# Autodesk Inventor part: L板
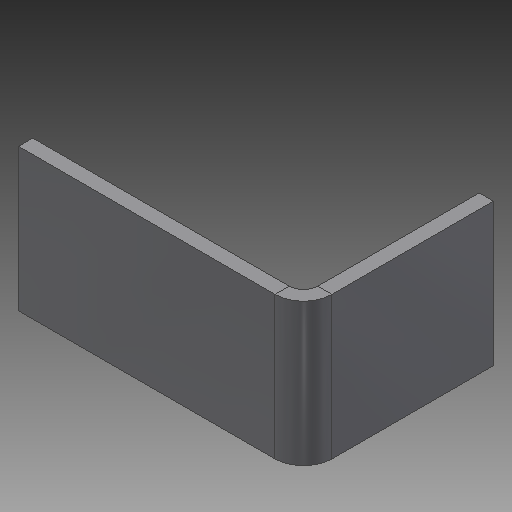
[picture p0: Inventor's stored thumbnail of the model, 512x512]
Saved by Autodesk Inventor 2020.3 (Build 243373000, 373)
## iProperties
RuleStatus: InUse
BeforeDocSave0: 重量提取
Part Number: L板
Material: Q235B
Description: Metal
Document SubType Name: 钣金
Density: 7.85 g/cm^3
Sheet Metal Rule: 默认_mm
Appearance: Q235B
Mass: 67.166 g
Surface Area: 64.5453 cm^2
Volume: 8.55617 cm^3
名称: L板
重量: 0.07
文件类型: 钣金件
规格材料: t3/Q235B
Author: 陈驹祥
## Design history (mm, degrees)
node "异形板1"
  sketch "草图3"
    geometry: L1 (0, 0)-(60, 0); L2 (0, 0)-(0, -40)
    constraints: 4 end point, 1 horizontal, 1 vertical
    dimensions: "LA" = 60 distance of L1.start L1.end; "LB" = 40 distance of L1.start L2.end
node "实体3"
feature "平板1" dims "d6" = 3 (= 厚度), "d7" = 3 (= 折弯释压宽度), "d8" = 1.5 (= 折弯释压深度), "d9" = 6 (= 最小余量), "d10" = 3 (= 过渡半径), "d12" = 3 (= 折弯半径), "d13" = 3, "d14" = 12 (= 拐角释压尺寸), "d15" = 3 (= 间隙大小), "d16" = 3 (= Jacobi半径尺寸), "LC" = 30, "焊缝间隙" = 0.01
feature "折弯1" dims "d6" = 3 (= 厚度), "d7" = 3 (= 折弯释压宽度), "d8" = 1.5 (= 折弯释压深度), "d9" = 6 (= 最小余量), "d10" = 3 (= 过渡半径), "d12" = 3 (= 折弯半径), "d13" = 3, "焊缝间隙" = 0.01
feature "拐角1" dims "d13" = 3, "d14" = 12 (= 拐角释压尺寸), "d15" = 3 (= 间隙大小), "d16" = 3 (= Jacobi半径尺寸)
other parameters: "厚度" = 3, "K系数" = 4.4, "折弯半径" = 3 (= 厚度), "折弯释压宽度" = 3 (= 厚度), "折弯释压深度" = 1.5 (= 0.5 x 厚度), "拐角释压尺寸" = 12 (= 4 x 厚度), "最小余量" = 6 (= 2 x 厚度), "过渡半径" = 3 (= 折弯半径), "Jacobi半径尺寸" = 3 (= 折弯半径), "间隙大小" = 3 (= 厚度)
